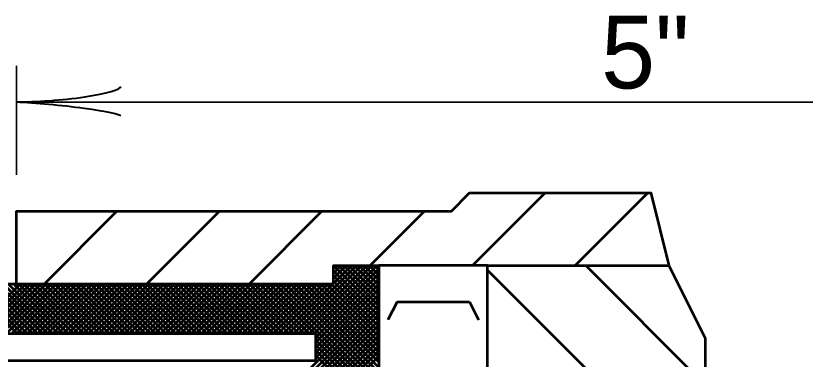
# Model space of a CAD drawing. Extents: x -1 to 679, y 0 to 440.
# Drawn here: x 306.43 to 328.21, y 358.75 to 368.21 of the extents above; entities that cross this region are included whole.
import ezdxf

# ---------------------------------------------------------------- set-up
doc = ezdxf.new("R2010")
doc.units = 0
doc.header["$LTSCALE"] = 0.8
doc.layers.add('1', color=7, linetype='Continuous', lineweight=53)

msp = doc.modelspace()

# ---------------------------------------------------------------- linework, layer by layer
at = {"layer": '1', "lineweight": 35}
for p, q in [((306.447, 363.8301), (306.447, 366.8301)), ((306.447, 365.8301), (340.4307, 365.8301))]:
    msp.add_line(p, q, dxfattribs=at)
at = {"layer": '1'}
for p, q in [((319.0333, 361.3301), (321.0333, 363.3301)), ((321.8618, 361.3301), (323.8618, 363.3301)), ((307.2197, 360.8301), (309.2197, 362.8301)), ((310.0481, 360.8301), (312.0481, 362.8301)), ((312.8765, 360.8301), (314.8765, 362.8301)), ((316.2049, 361.3301), (317.7049, 362.8301)), ((313.9542, 359.4551), (315.8292, 361.3301)), ((314.0957, 359.4551), (315.9707, 361.3301)), ((314.2371, 359.4551), (316.1121, 361.3301)), ((314.3785, 359.4551), (316.2535, 361.3301)), ((314.5199, 359.4551), (316.3949, 361.3301)), ((315.197, 361.2636), (315.2635, 361.3301)), ((315.197, 361.1222), (315.4049, 361.3301)), ((315.197, 360.9808), (315.5463, 361.3301)), ((315.197, 360.8393), (315.6877, 361.3301)), ((316.447, 360.0785), (315.197, 361.3285)), ((316.447, 360.2199), (315.3368, 361.3301)), ((316.447, 360.3613), (315.4783, 361.3301)), ((316.447, 360.5027), (315.6197, 361.3301)), ((316.447, 360.6442), (315.7611, 361.3301)), ((316.447, 360.7856), (315.9025, 361.3301)), ((316.447, 360.927), (316.0439, 361.3301)), ((316.447, 361.0684), (316.1853, 361.3301)), ((316.447, 361.2098), (316.3268, 361.3301)), ((319.447, 361.3301), (316.447, 361.3301)), ((325.447, 358.0356), (322.1525, 361.3301)), ((314.6613, 359.4551), (316.447, 361.2407)), ((316.447, 359.9371), (315.197, 361.1871)), ((324.8241, 355.8301), (319.447, 361.2072)), ((314.697, 359.3493), (316.447, 361.0993)), ((314.697, 359.2079), (316.447, 360.9579)), ((316.447, 359.7956), (315.197, 361.0456)), ((316.447, 359.6542), (315.197, 360.9042)), ((306.4638, 359.4551), (305.0888, 360.8301)), ((305.1861, 359.4551), (306.5611, 360.8301)), ((306.6052, 359.4551), (305.2302, 360.8301)), ((305.3275, 359.4551), (306.7025, 360.8301)), ((306.7466, 359.4551), (305.3716, 360.8301)), ((305.4689, 359.4551), (306.8439, 360.8301)), ((306.8881, 359.4551), (305.5131, 360.8301)), ((305.6103, 359.4551), (306.9853, 360.8301)), ((307.0295, 359.4551), (305.6545, 360.8301)), ((305.7518, 359.4551), (307.1268, 360.8301)), ((307.1709, 359.4551), (305.7959, 360.8301)), ((305.8932, 359.4551), (307.2682, 360.8301)), ((307.3123, 359.4551), (305.9373, 360.8301)), ((306.0346, 359.4551), (307.4096, 360.8301)), ((307.4538, 359.4551), (306.0788, 360.8301)), ((306.176, 359.4551), (307.551, 360.8301)), ((307.5952, 359.4551), (306.2202, 360.8301)), ((306.3174, 359.4551), (307.6924, 360.8301)), ((307.7366, 359.4551), (306.3616, 360.8301)), ((306.4588, 359.4551), (307.8338, 360.8301)), ((307.878, 359.4551), (306.503, 360.8301)), ((306.6003, 359.4551), (307.9753, 360.8301)), ((308.0194, 359.4551), (306.6444, 360.8301)), ((306.7417, 359.4551), (308.1167, 360.8301)), ((308.1608, 359.4551), (306.7858, 360.8301)), ((306.8832, 359.4551), (308.2582, 360.8301)), ((308.3023, 359.4551), (306.9273, 360.8301)), ((307.0246, 359.4551), (308.3996, 360.8301)), ((308.4437, 359.4551), (307.0687, 360.8301)), ((307.166, 359.4551), (308.541, 360.8301)), ((308.5851, 359.4551), (307.2101, 360.8301)), ((307.3074, 359.4551), (308.6824, 360.8301)), ((308.7265, 359.4551), (307.3515, 360.8301)), ((307.4488, 359.4551), (308.8238, 360.8301)), ((308.8679, 359.4551), (307.4929, 360.8301)), ((307.5902, 359.4551), (308.9652, 360.8301)), ((309.0093, 359.4551), (307.6343, 360.8301)), ((307.7317, 359.4551), (309.1067, 360.8301)), ((309.1508, 359.4551), (307.7758, 360.8301)), ((307.8731, 359.4551), (309.2481, 360.8301)), ((309.2922, 359.4551), (307.9172, 360.8301)), ((308.0145, 359.4551), (309.3895, 360.8301)), ((309.4337, 359.4551), (308.0587, 360.8301)), ((308.1559, 359.4551), (309.5309, 360.8301)), ((309.5751, 359.4551), (308.2001, 360.8301)), ((308.2973, 359.4551), (309.6723, 360.8301)), ((309.7165, 359.4551), (308.3415, 360.8301)), ((308.4387, 359.4551), (309.8137, 360.8301)), ((309.8579, 359.4551), (308.4829, 360.8301)), ((308.5802, 359.4551), (309.9552, 360.8301)), ((309.9993, 359.4551), (308.6243, 360.8301)), ((308.7216, 359.4551), (310.0966, 360.8301)), ((310.1407, 359.4551), (308.7657, 360.8301)), ((308.863, 359.4551), (310.238, 360.8301)), ((310.2822, 359.4551), (308.9072, 360.8301)), ((309.0044, 359.4551), (310.3794, 360.8301)), ((310.4236, 359.4551), (309.0486, 360.8301)), ((309.1459, 359.4551), (310.5209, 360.8301)), ((310.565, 359.4551), (309.19, 360.8301)), ((309.2873, 359.4551), (310.6623, 360.8301)), ((310.7064, 359.4551), (309.3314, 360.8301)), ((309.4287, 359.4551), (310.8037, 360.8301)), ((310.8478, 359.4551), (309.4728, 360.8301)), ((309.5702, 359.4551), (310.9452, 360.8301)), ((310.9892, 359.4551), (309.6142, 360.8301)), ((309.7116, 359.4551), (311.0866, 360.8301)), ((311.1307, 359.4551), (309.7557, 360.8301)), ((309.853, 359.4551), (311.228, 360.8301)), ((311.2721, 359.4551), (309.8971, 360.8301)), ((309.9944, 359.4551), (311.3694, 360.8301)), ((311.4135, 359.4551), (310.0385, 360.8301)), ((310.1358, 359.4551), (311.5108, 360.8301)), ((311.5549, 359.4551), (310.1799, 360.8301)), ((310.2772, 359.4551), (311.6522, 360.8301)), ((311.6963, 359.4551), (310.3213, 360.8301)), ((310.4187, 359.4551), (311.7937, 360.8301)), ((311.8378, 359.4551), (310.4628, 360.8301)), ((310.5601, 359.4551), (311.9351, 360.8301)), ((311.9792, 359.4551), (310.6042, 360.8301)), ((310.7015, 359.4551), (312.0765, 360.8301)), ((312.1207, 359.4551), (310.7457, 360.8301)), ((310.8429, 359.4551), (312.2179, 360.8301)), ((312.2621, 359.4551), (310.8871, 360.8301)), ((310.9843, 359.4551), (312.3593, 360.8301)), ((312.4035, 359.4551), (311.0285, 360.8301)), ((311.1257, 359.4551), (312.5007, 360.8301)), ((312.5449, 359.4551), (311.1699, 360.8301)), ((311.2672, 359.4551), (312.6422, 360.8301)), ((312.6863, 359.4551), (311.3113, 360.8301)), ((311.4086, 359.4551), (312.7836, 360.8301)), ((312.8277, 359.4551), (311.4527, 360.8301)), ((311.5501, 359.4551), (312.9251, 360.8301)), ((312.9692, 359.4551), (311.5942, 360.8301)), ((311.6915, 359.4551), (313.0665, 360.8301)), ((313.1106, 359.4551), (311.7356, 360.8301)), ((311.8329, 359.4551), (313.2079, 360.8301)), ((313.252, 359.4551), (311.877, 360.8301)), ((311.9743, 359.4551), (313.3493, 360.8301)), ((313.3934, 359.4551), (312.0184, 360.8301)), ((312.1157, 359.4551), (313.4907, 360.8301)), ((313.5348, 359.4551), (312.1598, 360.8301)), ((312.2572, 359.4551), (313.6322, 360.8301)), ((313.6762, 359.4551), (312.3012, 360.8301)), ((312.3986, 359.4551), (313.7736, 360.8301)), ((313.8177, 359.4551), (312.4427, 360.8301)), ((312.54, 359.4551), (313.915, 360.8301)), ((313.9591, 359.4551), (312.5841, 360.8301)), ((312.6814, 359.4551), (314.0564, 360.8301)), ((314.1005, 359.4551), (312.7255, 360.8301)), ((312.8228, 359.4551), (314.1978, 360.8301)), ((314.2419, 359.4551), (312.8669, 360.8301)), ((312.9642, 359.4551), (314.3392, 360.8301)), ((314.3834, 359.4551), (313.0084, 360.8301)), ((313.1057, 359.4551), (314.4807, 360.8301)), ((314.5248, 359.4551), (313.1498, 360.8301)), ((313.2471, 359.4551), (314.6221, 360.8301)), ((314.6662, 359.4551), (313.2912, 360.8301)), ((313.3885, 359.4551), (314.7635, 360.8301)), ((316.447, 357.8157), (313.4327, 360.8301)), ((313.5299, 359.4551), (314.9049, 360.8301)), ((316.447, 357.9572), (313.5741, 360.8301)), ((313.6713, 359.4551), (315.0463, 360.8301)), ((316.447, 358.0986), (313.7155, 360.8301)), ((313.8127, 359.4551), (315.1877, 360.8301)), ((316.447, 358.24), (313.8569, 360.8301)), ((316.447, 358.3814), (313.9983, 360.8301)), ((316.447, 358.5228), (314.1397, 360.8301)), ((316.447, 358.6642), (314.2812, 360.8301)), ((316.447, 358.8057), (314.4226, 360.8301)), ((316.447, 358.9471), (314.564, 360.8301)), ((314.697, 359.0665), (316.447, 360.8165)), ((314.697, 358.9251), (316.447, 360.6751)), ((316.447, 359.0885), (314.7054, 360.8301)), ((316.447, 359.2299), (314.8468, 360.8301)), ((316.447, 359.3713), (314.9882, 360.8301)), ((316.447, 359.5127), (315.1297, 360.8301)), ((314.697, 358.7837), (316.447, 360.5337)), ((313.3848, 357.3301), (316.447, 360.3922)), ((313.5263, 357.3301), (316.447, 360.2508)), ((316.947, 360.3301), (316.697, 359.8301)), ((316.947, 360.3301), (318.947, 360.3301)), ((318.947, 360.3301), (319.197, 359.8301)), ((313.6677, 357.3301), (316.447, 360.1094)), ((313.8091, 357.3301), (316.447, 359.968)), ((313.9505, 357.3301), (316.447, 359.8266)), ((314.0919, 357.3301), (316.447, 359.6852)), ((314.2333, 357.3301), (316.447, 359.5437)), ((314.3748, 357.3301), (316.447, 359.4023)), ((316.447, 357.6743), (314.697, 359.4243)), ((314.5163, 357.3301), (316.447, 359.2608)), ((316.447, 357.5329), (314.697, 359.2829)), ((316.447, 357.3915), (314.697, 359.1415)), ((314.6577, 357.3301), (316.447, 359.1194)), ((316.447, 357.25), (314.697, 359)), ((314.697, 357.228), (316.447, 358.978)), ((316.447, 357.1086), (314.697, 358.8586)), ((314.697, 357.0866), (316.447, 358.8366))]:
    msp.add_line(p, q, dxfattribs=at)
for points in [[(306.447, 360.8301), (306.447, 362.8301), (318.447, 362.8301), (318.947, 363.3301), (323.947, 363.3301), (324.447, 361.3301)], [(319.447, 352.5801), (319.447, 356.5801), (319.447, 361.3301), (324.447, 361.3301), (325.447, 359.3301), (325.447, 355.8301), (323.947, 355.8301), (322.947, 355.8301)]]:
    msp.add_lwpolyline(points, dxfattribs=at)
for points in [[(295.697, 358.4551), (295.697, 359.7051), (295.697, 360.8301), (306.447, 360.8301), (315.197, 360.8301), (315.197, 361.3301), (316.447, 361.3301), (316.447, 347.8301), (315.197, 347.8301), (315.197, 348.3301), (306.447, 348.3301), (295.697, 348.3301), (295.697, 349.4551), (295.697, 350.7051), (295.697, 351.8301), (306.447, 351.8301), (314.697, 351.8301), (314.697, 357.3301), (306.447, 357.3301), (295.697, 357.3301)], [(296.197, 358.7051), (296.197, 359.4551), (314.697, 359.4551), (314.697, 358.7051)]]:
    msp.add_lwpolyline(points, close=True, dxfattribs=at)
at = {"layer": '1', "lineweight": 40}
for centre, major_axis, ratio, start_param, end_param in [((307.5382, 366.1064), (-1.7857, -0.1562), 0.122415, 0.8963533, 3.1415927), ((307.5382, 366.1064), (-1.7857, -0.1562), 0.122415, 0.8963533, 3.1415927), ((307.5675, 365.6185), (-1.7565, 0.1757), 0.07063, 3.1407148, 5.41811), ((307.5675, 365.6185), (-1.7565, 0.1757), 0.07063, 3.1407148, 5.41811)]:
    msp.add_ellipse(centre, major_axis=major_axis, ratio=ratio, start_param=start_param, end_param=end_param, dxfattribs=at)

# ---------------------------------------------------------------- texts
at = {"layer": '1'}
msp.add_text('5"', height=2, dxfattribs=at).set_placement((322.5782, 366.2091))

doc.saveas('drawing.dxf')
